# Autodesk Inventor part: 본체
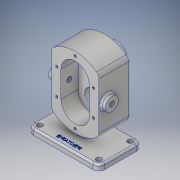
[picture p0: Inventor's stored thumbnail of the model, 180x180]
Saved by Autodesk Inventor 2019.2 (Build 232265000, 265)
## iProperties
Created: 2019-03
Part Number: 본체
Material: 알루미늄 6061
Document SubType Name: Modeling
Designer: User
Density: 2.7 g/cm^3
Appearance: 알루미늄 - 평지
Mass: 1187.12 g
Surface Area: 719.257 cm^2
Volume: 439.673 cm^3
Author: User
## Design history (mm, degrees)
sketch "스케치1"
  geometry: L1 (60, 36.5)-(-60, 36.5); L2 (-60, 36.5)-(-60, -36.5); L3 (-60, -36.5)-(60, -36.5); L4 (60, -36.5)-(60, 36.5); L5 (60, 36.5)-(-60, -36.5); L6 (-60, 36.5)-(60, -36.5); 1 further point
  constraints: 12 end point, 2 midpoint, 2 parallel, 1 horizontal, 1 perpendicular
  dimensions: "d0" = 73 distance between parallel lines of L1 L3; "d1" = 120 distance of L1.start L1.end
extrude "돌출1" new body sketch "스케치1" distance "d2" = 10; taper "d3" = 0 deg
sketch "스케치2"
  geometry: L1 (-6, 36.5)-(6, 36.5); L2 (6, 36.5)-(6, -6.5); L3 (6, -6.5)-(-6, -6.5); L4 (-6, -6.5)-(-6, 36.5); L5 (60, 36.5)-(-60, 36.5) reference; 1 further point
  constraints: 8 end point, 2 parallel, 1 collinear, 1 horizontal, 1 perpendicular
  dimensions: "d4" = 12 distance between parallel lines of L2 L4; "d5" = 6 distance from line of point (0, 0) L4; "d6" = 43 distance between parallel lines of L5 L3
extrude "돌출2" join sketch "스케치2" distance "d7" = 68; taper "d8" = 0 deg
sketch "스케치3"
  geometry: L1 (0, 0)-(120, 0) reference; L2 (100, 122.721)-(100, 33.279); L3 (20, 33.279)-(20, 122.721); L4 (-28, 78)-(188, 78); L5 (54, 78)-(66, 78) reference; A1 r 60 centre (60, 78) between (100, 122.721) and (20, 122.721); A2 r 60 centre (60, 78) between (20, 33.279) and (100, 33.279); 2 further points
  constraints: 6 end point, 4 point on circle, 2 centre point, 2 midpoint, 1 horizontal, 1 parallel, 1 perpendicular
  dimensions: "d10" = 78 distance between parallel lines of L1 L4; "d12" = 80 distance between parallel lines of L2 L3; "d13" = 40 distance from line of A1.centre L3; "d14" = 60 radius of A1; "d15" = 60 radius of A2
extrude "돌출3" join sketch "스케치3" distance "d16" = 53; taper "d17" = 0 deg
sketch "스케치4"
  geometry: L1 (0, 0)-(120, 0) reference; C1 r 19 at (60, 100); 2 further points
  constraints: 1 centre point, 1 midpoint, 1 vertical alignment
  dimensions: "d18" = 38 diameter of C1; "d47" = 100 distance from line of L1 C1.centre
extrude "돌출4" join sketch "스케치4" distance "d19" = 17; taper "d20" = 0 deg
sketch "스케치5"
  geometry: L1 (-60, 100)-(-60, 56); L2 (-84, 100)-(-84, 56); L3 (-36, 56)-(-36, 100); L4 (-120, 0)-(0, 0) reference; L5 (-135, 78)-(56, 78); A1 r 24 centre (-60, 100) between (-36, 100) and (-84, 100); A2 r 24 centre (-60, 56) between (-84, 56) and (-36, 56); 3 further points
  constraints: 10 end point, 4 point on circle, 4 tangent, 2 centre point, 2 midpoint, 1 horizontal, 1 parallel, 1 point on line, 1 vertical, 1 vertical alignment
  dimensions: "d21" = 24 radius of A1; "d22" = 44 distance of L1.start L1.end; "d23" = 78 distance between parallel lines of L4 L5
extrude "돌출5" cut sketch "스케치5" distance "d24" = 29; taper "d25" = 0 deg
sketch "스케치6"
  geometry: 1 further point
sketch "스케치7"
  geometry: A1 r 24 centre (-60, 56) between (-84, 56) and (-36, 56) reference; 2 further points
  constraints: 1 coincident
hole "구멍1" sketch "스케치7" at (-60, 56) diameter "d26" = 25; stored, may be unused: countersink angle "d30" = 90 deg, drill point angle "d32" = 0 deg; dims "d27" = 20, "d28" = 4, "d29" = 2, "d31" = 15
sketch "스케치8"
  geometry: A1 r 24 centre (-60, 100) between (-36, 100) and (-84, 100) reference; 2 further points
  constraints: 1 coincident
hole "구멍2" sketch "스케치8" at (-60, 100) diameter "d33" = 25; stored, may be unused: countersink angle "d37" = 90 deg, drill point angle "d39" = 0 deg; dims "d34" = 20, "d35" = 4, "d36" = 2, "d38" = 15
sketch "스케치9"
  geometry: C1 r 12.5 at (0, 0) reference; 2 further points
  constraints: 1 coincident
hole "구멍3" sketch "스케치9" at (0, 0) diameter "d40" = 17; stored, may be unused: countersink angle "d44" = 90 deg, drill point angle "d46" = 0 deg; dims "d41" = 20, "d42" = 4, "d43" = 2, "d45" = 15
sketch "스케치10"
  geometry: C1 r 12.5 at (0, 0) reference; C2 r 14 at (0, 0); 1 further point
  constraints: 1 centre point, 1 coincident
  dimensions: "d48" = 28 diameter of C2
extrude "돌출6" cut sketch "스케치10" distance "d49" = 7.3; taper "d50" = 0 deg
chamfer "모따기1" distance "d51" = 0.7; stored, may be unused: second distance "d52" = 2, angle "d53" = 30 deg
fillet "모깎기1" dims "d54" = 0.5
sketch "스케치11"
  geometry: L1 (-73, -33.279)-(0, -33.279) reference; L2 (-53, 0)-(-53, 89.443) reference; C1 r 11 at (-39, 44.721); 1 further point
  constraints: 1 centre point
  dimensions: "d55" = 22 diameter of C1; "d56" = 78 distance from line of L1 C1.centre; "d57" = 14 distance from line of L2 C1.centre
extrude "돌출7" join sketch "스케치11" distance "d58" = 8; taper "d59" = 0 deg
sketch "스케치12"
  geometry: C1 r 11 at (0, 0) reference; 2 further points
  constraints: 1 coincident
hole "구멍4" sketch "스케치12" at (0, 0) diameter "d60" = 8.376; stored, may be unused: countersink angle "d64" = 90 deg, drill point angle "d66" = 0 deg; dims "d61" = 100, "d62" = 4, "d63" = 2, "d65" = 27.3
sketch "스케치13"
  geometry: L1 (-120, 0)-(0, 0) reference; L2 (-126, 78)-(26, 78); C1 r 5.385 at (-60, 131); C2 r 8.5 at (-60, 100) reference; C3 r 5.385 at (-60, 25); 2 further points
  constraints: 2 centre point, 2 end point, 1 horizontal, 1 midpoint, 1 symmetric about line, 1 vertical alignment, 1 other
  dimensions: "d67" = 78 distance between parallel lines of L1 L2; "d69" = 31 distance of C1.centre C2.centre; "d70" = 10.77033 diameter of C1
sketch "스케치14"
  geometry: L1 (-153, 78)-(62, 78); L2 (-120, 0)-(0, 0) reference; L3 (-60, -27.6)-(-60, 165.6) reference; C1 r 6.403 at (-91, 100); C2 r 6 at (-29, 100); C3 r 6 at (-29, 56); C4 r 6.403 at (-91, 56); 1 further point
  constraints: 4 centre point, 2 end point, 2 symmetric about line, 1 horizontal, 1 horizontal alignment, 2 other
  dimensions: "d78" = 78 distance between parallel lines of L2 L1; "d79" = 22 distance from line of L1 C2.centre; "d80" = 31 distance from line of C2.centre L3; "d81" = 31 distance from line of L3 C1.centre; "d82" = 12 diameter of C2; "d83" = 12.80625 diameter of C1
sketch "스케치15"
  geometry: L1 (-60, 36.5)-(-60, -36.5) reference; L2 (-60, -36.5)-(60, -36.5) reference; C1 r 4.5 at (-50, -26.5); 1 further point
  constraints: 1 centre point
  dimensions: "d91" = 9 diameter of C1; "d92" = 10 distance from line of L1 C1.centre; "d93" = 10 distance from line of L2 C1.centre
extrude "돌출8" cut sketch "스케치15" extent not by distance; stored distance "d94" = 8; taper "d95" = 0 deg
fillet "모깎기2" dims "d96" = 10
fillet "모깎기3" dims "d97" = 10
fillet "모깎기7" dims "d101" = 3
chamfer "모따기2" distance "d102" = 1; stored, may be unused: second distance "d103" = 2, angle "d104" = 30 deg
fillet "모깎기8" dims "d105" = 3
fillet "모깎기9" dims "d106" = 3
fillet "모깎기10" dims "d107" = 3
fillet "모깎기11" dims "d108" = 3
sketch "스케치16"
  geometry: L1 (-60, 26.5)-(-60, -26.5) reference; L2 (-50, -36.5)-(50, -36.5) reference; 2 further points
  constraints: 1 other
  dimensions: "d109" = 60 distance from line of L1 point (0, -26.5); "d110" = 10 distance from line of L2 point (0, -26.5)
feature "엠보싱1" sketch "스케치16" dims "d111" = 0.5, "d112" = 0
hole "구멍7" sketch "스케치13" diameter "d113" = 4.134; stored, may be unused: countersink angle "d117" = 90 deg, drill point angle "d119" = 118 deg; dims "d114" = 10, "d115" = 4, "d116" = 2, "d118" = 12
hole "구멍8" sketch "스케치14" diameter "d120" = 4.134; stored, may be unused: countersink angle "d124" = 90 deg, drill point angle "d126" = 118 deg; dims "d121" = 10, "d122" = 4, "d123" = 2, "d125" = 12
node "솔리드1"
mirror "미러1"
mirror "미러2"
mirror "미러3"
